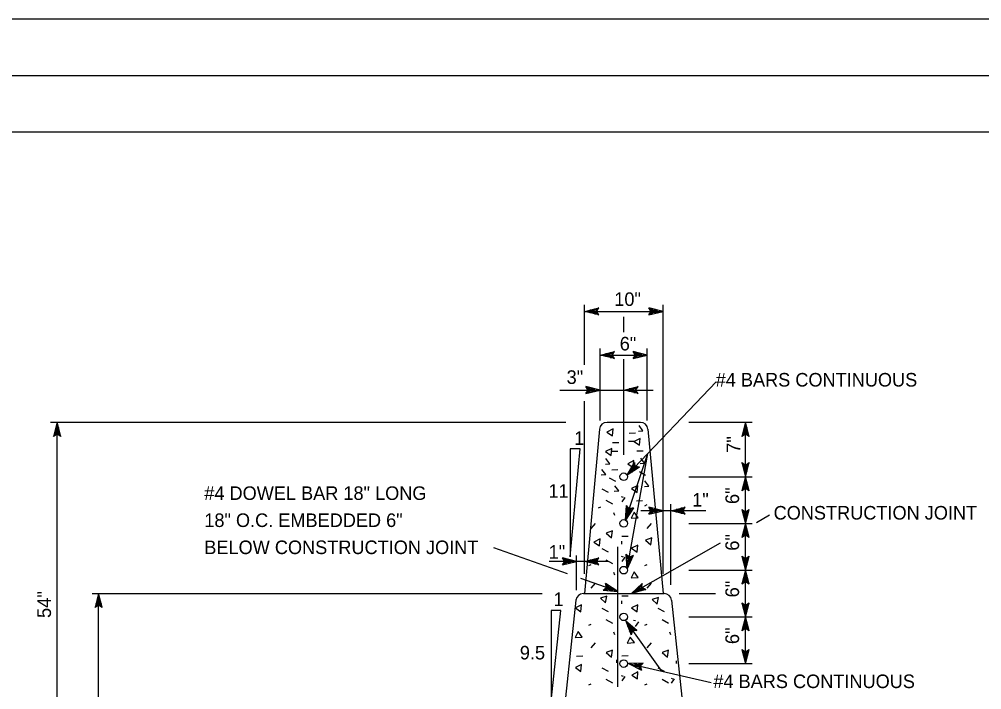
# Model space of a CAD drawing. Extents: x 504255 to 505955, y 659986 to 661086.
# Drawn here: x 504611.9 to 505019.2, y 660802.7 to 661086.4 of the extents above; entities that cross this region are included whole.
import ezdxf

# ---------------------------------------------------------------- set-up
doc = ezdxf.new("R2010")
doc.units = 0
for name, color, linetype in [('Level 62', 7, 'Continuous'), ('Level1', 7, 'Continuous'), ('Level3', 7, 'Continuous'), ('Level63', 7, 'Continuous')]:
    doc.layers.add(name, color=color, linetype=linetype)

msp = doc.modelspace()

# ---------------------------------------------------------------- linework, layer by layer
at = {"layer": 'Level 62'}
msp.add_lwpolyline([(505955.48, 661086.39), (504255.48, 661086.39), (504255.48, 659986.39), (505955.48, 659986.39)], close=True, dxfattribs=at)
at = {"layer": 'Level1'}
for p, q in [((504851.06, 660940.25), (504851.06, 660965.56)), ((504884.31, 660851.82), (504884.31, 660965.56)), ((504851.06, 660962.8), (504884.31, 660962.8)), ((504867.69, 660954), (504867.69, 660960.5)), ((504857.71, 660916.58), (504857.71, 660947.1)), ((504877.66, 660916.58), (504877.66, 660947.1)), ((504857.71, 660944.33), (504877.66, 660944.33)), ((504867.69, 660902.12), (504867.69, 660942.56)), ((504869.16, 660893.53), (504906.75, 660933.02)), ((504840.66, 660929.49), (504880.16, 660929.49)), ((504851.06, 660851.82), (504851.06, 660924.85)), ((504625.17, 660915.87), (504843.24, 660915.87)), ((504627.96, 660738.11), (504627.96, 660915.87)), ((504895.17, 660915.87), (504922.02, 660915.87)), ((504919.22, 660892.83), (504919.22, 660915.87)), ((504857.45, 660913), (504851.06, 660843.45)), ((504877.92, 660913), (504884.31, 660843.45)), ((504845.06, 660858.99), (504849.26, 660904.65)), ((504845.06, 660904.65), (504845.06, 660858.99)), ((504849.26, 660904.65), (504845.06, 660904.65)), ((504868.44, 660874.51), (504877.87, 660902.68)), ((504869.2, 660853.92), (504877.87, 660902.68)), ((504895.17, 660892.83), (504922.02, 660892.83)), ((504919.22, 660873.08), (504919.22, 660892.83)), ((504884.31, 660878.49), (504874.94, 660878.49)), ((504902.45, 660878.49), (504884.31, 660878.49)), ((504887.62, 660847.14), (504887.62, 660881.26)), ((504923.88, 660873.56), (504929.33, 660876.67)), ((504895.17, 660873.08), (504922.02, 660873.08)), ((504919.22, 660853.33), (504919.22, 660873.08)), ((504843.9, 660851.74), (504812.69, 660862.72)), ((504865.17, 660803.96), (504865.17, 660863.21)), ((504871.03, 660843.45), (504908.65, 660864.88)), ((504847.75, 660844.93), (504847.75, 660859.58)), ((504847.75, 660857.04), (504836.13, 660857.04)), ((504861.02, 660857.04), (504847.75, 660857.04)), ((504865.17, 660844.26), (504849.54, 660849.76)), ((504895.17, 660853.33), (504922.02, 660853.33)), ((504919.22, 660833.58), (504919.22, 660853.33)), ((504642.72, 660843.45), (504833.18, 660843.45)), ((504645.51, 660738.11), (504645.51, 660843.45)), ((504891.09, 660843.45), (504906.46, 660843.45)), ((504836.94, 660797.95), (504841, 660836.25)), ((504841, 660836.25), (504836.94, 660836.25)), ((504836.94, 660836.25), (504836.94, 660797.95)), ((504895.17, 660833.58), (504922.02, 660833.58)), ((504919.22, 660813.83), (504919.22, 660833.58)), ((504868.53, 660831.75), (504883.68, 660810.65)), ((504869.72, 660813.87), (504904.71, 660805.81)), ((504895.17, 660813.83), (504922.02, 660813.83))]:
    msp.add_line(p, q, dxfattribs=at)
for points in [[(504257.9, 660010.3), (505953.07, 660010.3), (505953.07, 661062.47), (504257.9, 661062.47), (504257.9, 660010.3)], [(504327.92, 660023.67), (505946.29, 660023.67), (505946.29, 661038.56), (504327.92, 661038.56), (504327.92, 660023.67)], [(504857.1, 660961.3), (504851.06, 660962.8), (504857.1, 660964.29), (504856.39, 660963.79), (504855.35, 660963.79), (504856.36, 660963.3), (504853.34, 660963.3), (504856.02, 660962.8), (504853.34, 660962.3), (504856.36, 660962.3), (504855.35, 660961.8), (504856.39, 660961.8), (504857.1, 660961.3), (504856.09, 660962.8), (504857.1, 660964.29)], [(504878.27, 660961.3), (504884.31, 660962.8), (504878.27, 660964.29), (504878.98, 660963.79), (504880.02, 660963.79), (504879.01, 660963.3), (504882.03, 660963.3), (504879.35, 660962.8), (504882.03, 660962.3), (504879.01, 660962.3), (504880.02, 660961.8), (504878.98, 660961.8), (504878.27, 660961.3), (504879.28, 660962.8), (504878.27, 660964.29)], [(504863.75, 660942.84), (504857.71, 660944.33), (504863.75, 660945.84), (504863.04, 660945.34), (504862.01, 660945.34), (504863.01, 660944.84), (504859.99, 660944.84), (504862.67, 660944.33), (504859.99, 660943.84), (504863.01, 660943.84), (504862.01, 660943.34), (504863.04, 660943.34), (504863.75, 660942.84), (504862.74, 660944.33), (504863.75, 660945.84)], [(504871.62, 660942.84), (504877.66, 660944.33), (504871.62, 660945.84), (504872.33, 660945.34), (504873.37, 660945.34), (504872.36, 660944.84), (504875.38, 660944.84), (504872.7, 660944.33), (504875.38, 660943.84), (504872.36, 660943.84), (504873.37, 660943.34), (504872.33, 660943.34), (504871.62, 660942.84), (504872.62, 660944.33), (504871.62, 660945.84)], [(504851.67, 660928), (504857.71, 660929.49), (504851.67, 660931), (504852.38, 660930.5), (504853.42, 660930.5), (504852.41, 660930), (504855.43, 660930), (504852.75, 660929.49), (504855.43, 660929), (504852.41, 660929), (504853.42, 660928.5), (504852.38, 660928.5), (504851.67, 660928), (504852.68, 660929.49), (504851.67, 660931)], [(504873.73, 660928), (504867.69, 660929.49), (504873.73, 660931), (504873.02, 660930.5), (504871.98, 660930.5), (504872.98, 660930), (504869.96, 660930), (504872.64, 660929.49), (504869.96, 660929), (504872.98, 660929), (504871.98, 660928.5), (504873.02, 660928.5), (504873.73, 660928), (504872.72, 660929.49), (504873.73, 660931)], [(504629.47, 660909.89), (504627.96, 660915.87), (504626.45, 660909.89), (504626.96, 660910.6), (504626.96, 660911.63), (504627.46, 660910.63), (504627.46, 660913.62), (504627.96, 660910.96), (504628.47, 660913.62), (504628.47, 660910.63), (504628.97, 660911.63), (504628.97, 660910.6), (504629.47, 660909.89), (504627.96, 660910.89), (504626.45, 660909.89)], [(504860.62, 660915.87), (504874.74, 660915.87)], [(504920.74, 660909.89), (504919.22, 660915.87), (504917.72, 660909.89), (504918.22, 660910.6), (504918.22, 660911.63), (504918.72, 660910.63), (504918.72, 660913.63), (504919.22, 660910.96), (504919.73, 660913.63), (504919.73, 660910.63), (504920.23, 660911.63), (504920.23, 660910.6), (504920.74, 660909.89), (504919.22, 660910.89), (504917.72, 660909.89)], [(504874.39, 660896.85), (504869.16, 660893.53), (504872.2, 660898.9), (504872.07, 660898.04), (504871.36, 660897.29), (504872.42, 660897.68), (504870.35, 660895.5), (504872.55, 660897.1), (504871.07, 660894.82), (504873.15, 660897), (504872.82, 660895.92), (504873.53, 660896.68), (504874.39, 660896.85), (504872.6, 660897.15), (504872.2, 660898.9)], [(504917.71, 660898.81), (504919.22, 660892.83), (504920.74, 660898.81), (504920.23, 660898.1), (504920.23, 660897.07), (504919.73, 660898.07), (504919.73, 660895.08), (504919.22, 660897.74), (504918.72, 660895.08), (504918.72, 660898.07), (504918.21, 660897.07), (504918.21, 660898.1), (504917.71, 660898.81), (504919.22, 660897.81), (504920.74, 660898.81)], [(504920.74, 660886.85), (504919.22, 660892.83), (504917.72, 660886.85), (504918.22, 660887.56), (504918.22, 660888.59), (504918.72, 660887.59), (504918.72, 660890.59), (504919.22, 660887.92), (504919.73, 660890.59), (504919.73, 660887.59), (504920.23, 660888.59), (504920.23, 660887.56), (504920.74, 660886.85), (504919.22, 660887.85), (504917.72, 660886.85)], [(504871.77, 660879.71), (504868.44, 660874.51), (504868.9, 660880.65), (504869.16, 660879.82), (504868.83, 660878.84), (504869.62, 660879.64), (504868.68, 660876.79), (504870, 660879.16), (504869.63, 660876.48), (504870.58, 660879.32), (504870.74, 660878.22), (504871.06, 660879.2), (504871.77, 660879.71), (504870.02, 660879.23), (504868.9, 660880.65)], [(504878.27, 660877), (504884.31, 660878.49), (504878.27, 660879.99), (504878.98, 660879.5), (504880.02, 660879.5), (504879.01, 660879), (504882.03, 660879), (504879.35, 660878.49), (504882.03, 660877.99), (504879.01, 660877.99), (504880.02, 660877.5), (504878.98, 660877.5), (504878.27, 660877), (504879.28, 660878.49), (504878.27, 660879.99)], [(504893.66, 660877), (504887.62, 660878.49), (504893.66, 660879.99), (504892.95, 660879.5), (504891.91, 660879.5), (504892.92, 660879), (504889.9, 660879), (504892.58, 660878.49), (504889.9, 660877.99), (504892.92, 660877.99), (504891.91, 660877.5), (504892.95, 660877.5), (504893.66, 660877), (504892.66, 660878.49), (504893.66, 660879.99)], [(504917.71, 660879.06), (504919.22, 660873.08), (504920.74, 660879.06), (504920.23, 660878.35), (504920.23, 660877.32), (504919.73, 660878.32), (504919.73, 660875.33), (504919.22, 660877.99), (504918.72, 660875.33), (504918.72, 660878.32), (504918.21, 660877.32), (504918.21, 660878.35), (504917.71, 660879.06), (504919.22, 660878.06), (504920.74, 660879.06)], [(504920.74, 660867.1), (504919.22, 660873.08), (504917.72, 660867.1), (504918.22, 660867.81), (504918.22, 660868.84), (504918.72, 660867.84), (504918.72, 660870.84), (504919.22, 660868.18), (504919.73, 660870.84), (504919.73, 660867.84), (504920.23, 660868.84), (504920.23, 660867.81), (504920.74, 660867.1), (504919.22, 660868.1), (504917.72, 660867.1)], [(504841.71, 660855.55), (504847.75, 660857.04), (504841.71, 660858.54), (504842.42, 660858.05), (504843.45, 660858.05), (504842.45, 660857.55), (504845.47, 660857.55), (504842.79, 660857.04), (504845.47, 660856.54), (504842.45, 660856.54), (504843.45, 660856.05), (504842.42, 660856.05), (504841.71, 660855.55), (504842.71, 660857.04), (504841.71, 660858.54)], [(504857.1, 660855.55), (504851.06, 660857.04), (504857.1, 660858.54), (504856.39, 660858.05), (504855.35, 660858.05), (504856.36, 660857.55), (504853.34, 660857.55), (504856.02, 660857.04), (504853.34, 660856.54), (504856.36, 660856.54), (504855.35, 660856.05), (504856.39, 660856.05), (504857.1, 660855.55), (504856.09, 660857.04), (504857.1, 660858.54)], [(504871.73, 660859.55), (504869.2, 660853.92), (504868.76, 660860.07), (504869.13, 660859.29), (504868.95, 660858.27), (504869.62, 660859.17), (504869.1, 660856.22), (504870.05, 660858.75), (504870.09, 660856.04), (504870.61, 660858.99), (504870.93, 660857.93), (504871.11, 660858.94), (504871.73, 660859.55), (504870.07, 660858.83), (504868.76, 660860.07)], [(504917.71, 660859.31), (504919.22, 660853.33), (504920.74, 660859.31), (504920.23, 660858.6), (504920.23, 660857.57), (504919.73, 660858.57), (504919.73, 660855.58), (504919.22, 660858.24), (504918.72, 660855.58), (504918.72, 660858.57), (504918.21, 660857.57), (504918.21, 660858.6), (504917.71, 660859.31), (504919.22, 660858.31), (504920.74, 660859.31)], [(504920.74, 660847.35), (504919.22, 660853.33), (504917.72, 660847.35), (504918.22, 660848.06), (504918.22, 660849.09), (504918.72, 660848.09), (504918.72, 660851.09), (504919.22, 660848.42), (504919.73, 660851.09), (504919.73, 660848.09), (504920.23, 660849.09), (504920.23, 660848.06), (504920.74, 660847.35), (504919.22, 660848.35), (504917.72, 660847.35)], [(504858.98, 660844.85), (504865.17, 660844.26), (504859.99, 660847.66), (504860.49, 660846.96), (504861.47, 660846.61), (504860.35, 660846.48), (504863.2, 660845.47), (504860.5, 660845.9), (504862.87, 660844.54), (504860.02, 660845.54), (504860.8, 660844.74), (504859.82, 660845.09), (504858.98, 660844.85), (504860.43, 660845.93), (504859.99, 660847.66)], [(504877.02, 660845.14), (504871.03, 660843.45), (504875.51, 660847.73), (504875.14, 660846.95), (504874.24, 660846.42), (504875.37, 660846.49), (504872.75, 660845), (504875.33, 660845.9), (504873.25, 660844.14), (504875.87, 660845.63), (504875.25, 660844.7), (504876.15, 660845.22), (504877.02, 660845.14), (504875.39, 660845.94), (504875.51, 660847.73)], [(504647.03, 660837.48), (504645.51, 660843.45), (504644, 660837.48), (504644.51, 660838.19), (504644.51, 660839.21), (504645.01, 660838.22), (504645.01, 660841.21), (504645.51, 660838.55), (504646.02, 660841.21), (504646.02, 660838.22), (504646.52, 660839.21), (504646.52, 660838.19), (504647.03, 660837.48), (504645.51, 660838.48), (504644, 660837.48)], [(504850.6, 660843.45), (504884.76, 660843.45)], [(504847.43, 660840.63), (504841.09, 660780.9)], [(504887.94, 660840.63), (504897.78, 660747.99)], [(504917.71, 660839.56), (504919.22, 660833.58), (504920.74, 660839.56), (504920.23, 660838.85), (504920.23, 660837.83), (504919.73, 660838.82), (504919.73, 660835.83), (504919.22, 660838.49), (504918.72, 660835.83), (504918.72, 660838.82), (504918.21, 660837.83), (504918.21, 660838.85), (504917.71, 660839.56), (504919.22, 660838.56), (504920.74, 660839.56)], [(504920.74, 660827.61), (504919.22, 660833.58), (504917.72, 660827.61), (504918.22, 660828.31), (504918.22, 660829.34), (504918.72, 660828.35), (504918.72, 660831.34), (504919.22, 660828.68), (504919.73, 660831.34), (504919.73, 660828.35), (504920.23, 660829.34), (504920.23, 660828.31), (504920.74, 660827.61), (504919.22, 660828.6), (504917.72, 660827.61)], [(504873.26, 660827.75), (504868.53, 660831.75), (504870.8, 660826.01), (504870.79, 660826.88), (504870.19, 660827.72), (504871.19, 660827.19), (504869.44, 660829.64), (504871.4, 660827.75), (504870.25, 660830.21), (504872.01, 660827.77), (504871.83, 660828.88), (504872.43, 660828.03), (504873.26, 660827.75), (504871.45, 660827.69), (504870.8, 660826.01)], [(504917.71, 660819.81), (504919.22, 660813.83), (504920.74, 660819.81), (504920.23, 660819.1), (504920.23, 660818.07), (504919.73, 660819.07), (504919.73, 660816.08), (504919.22, 660818.74), (504918.72, 660816.08), (504918.72, 660819.07), (504918.21, 660818.07), (504918.21, 660819.1), (504917.71, 660819.81), (504919.22, 660818.81), (504920.74, 660819.81)], [(504875.94, 660813.97), (504869.72, 660813.87), (504875.26, 660811.06), (504874.68, 660811.71), (504873.66, 660811.94), (504874.76, 660812.2), (504871.81, 660812.88), (504874.55, 660812.76), (504872.04, 660813.85), (504874.99, 660813.17), (504874.12, 660813.88), (504875.13, 660813.64), (504875.94, 660813.97), (504874.62, 660812.74), (504875.26, 660811.06)]]:
    msp.add_lwpolyline(points, dxfattribs=at)
for centre, start_param, end_param in [((504860.63, 660912.71), 4.712389, 6.192092), ((504874.75, 660912.71), 3.232686, 4.712389), ((504850.61, 660840.3), 4.712389, 6.178514), ((504884.77, 660840.3), 3.24706, 4.712389)]:
    msp.add_ellipse(centre, major_axis=(-3.19, 0), ratio=0.99, start_param=start_param, end_param=end_param, dxfattribs=at)
at = {"layer": 'Level3'}
for p, q in [((504872.64, 660911.23), (504870.03, 660911.19)), ((504865.59, 660907.21), (504862.98, 660907.16)), ((504872.29, 660907.8), (504869.67, 660907.75)), ((504865.24, 660903.54), (504862.62, 660903.49)), ((504875.87, 660903.66), (504873.26, 660903.61)), ((504865.24, 660895.72), (504862.62, 660895.68)), ((504874.31, 660895.08), (504876.92, 660893.54)), ((504861.54, 660892.45), (504864.19, 660891.04)), ((504858.43, 660887.71), (504861.08, 660886.3)), ((504860.18, 660882.99), (504862.92, 660881.38)), ((504867.58, 660884.14), (504866.8, 660884.37)), ((504868.17, 660884.14), (504866.85, 660882.28)), ((504875.63, 660882.59), (504873.02, 660882.54)), ((504857, 660879.66), (504857.94, 660880.1)), ((504876.64, 660880.61), (504877.58, 660881.05)), ((504863.29, 660877.73), (504863.84, 660876.59)), ((504855.55, 660873.09), (504853.71, 660870.97)), ((504879.25, 660873.09), (504877.42, 660870.97)), ((504869.54, 660867.56), (504866.93, 660867.51)), ((504858.43, 660862.46), (504861.08, 660861.05)), ((504866.8, 660865.58), (504866.8, 660864.39)), ((504860.18, 660857.73), (504862.92, 660856.12)), ((504867.58, 660858.89), (504866.8, 660859.12)), ((504868.17, 660858.89), (504866.85, 660857.03)), ((504852.94, 660855.36), (504853.88, 660855.79)), ((504876.64, 660855.36), (504877.58, 660855.79)), ((504863.29, 660852.48), (504863.84, 660851.34)), ((504855.55, 660847.84), (504853.71, 660845.71)), ((504879.25, 660847.84), (504877.42, 660845.71)), ((504869.54, 660842.31), (504866.93, 660842.26)), ((504858.43, 660837.2), (504861.08, 660835.79)), ((504866.8, 660840.32), (504866.8, 660839.14)), ((504882.13, 660837.2), (504884.78, 660835.79)), ((504852.94, 660830.11), (504853.88, 660830.54)), ((504860.18, 660832.47), (504862.92, 660830.87)), ((504872.61, 660831.84), (504871.83, 660832.07)), ((504873.88, 660831.41), (504872.56, 660829.56)), ((504876.64, 660830.11), (504877.58, 660830.54)), ((504883.88, 660832.47), (504886.62, 660830.87)), ((504863.29, 660827.22), (504863.84, 660826.08)), ((504886.98, 660827.22), (504887.54, 660826.08)), ((504855.55, 660822.58), (504853.71, 660820.46)), ((504879.25, 660822.58), (504877.42, 660820.46)), ((504850.34, 660816.9), (504847.72, 660816.84)), ((504869.54, 660817.05), (504866.93, 660817)), ((504864.62, 660815.38), (504864.62, 660814.19)), ((504889.9, 660815.01), (504889.9, 660813.83)), ((504858.43, 660811.95), (504861.08, 660810.54)), ((504882.13, 660811.95), (504884.78, 660810.54)), ((504852.94, 660804.86), (504853.88, 660805.28)), ((504860.18, 660807.22), (504862.92, 660805.61)), ((504867.58, 660808.38), (504866.8, 660808.61)), ((504868.17, 660808.38), (504866.85, 660806.53)), ((504876.64, 660804.86), (504877.58, 660805.28)), ((504883.88, 660807.22), (504886.62, 660805.61)), ((504889, 660807.32), (504887.69, 660805.46)), ((504888.66, 660807.2), (504887.87, 660807.43))]:
    msp.add_line(p, q, dxfattribs=at)
for points in [[(504860.57, 660911.76), (504862.9, 660910.16), (504863.18, 660913.1)], [(504872.04, 660907.73), (504874.37, 660906.14), (504874.65, 660909.08)], [(504859.97, 660903.47), (504862.31, 660901.87), (504862.59, 660904.82)], [(504869.41, 660898.38), (504871.74, 660896.79), (504872.02, 660899.73)], [(504870.97, 660887.85), (504873.3, 660886.25), (504873.58, 660889.19)], [(504872.04, 660877.84), (504870.85, 660875.3), (504873.83, 660875.52)], [(504862.97, 660869.92), (504860.29, 660869.03), (504862.5, 660867.04)], [(504855.04, 660865.2), (504857.36, 660863.61), (504857.65, 660866.55)], [(504879.61, 660866.96), (504876.93, 660866.07), (504879.14, 660864.08)], [(504870.97, 660862.59), (504873.3, 660861.01), (504873.58, 660863.94)], [(504872.04, 660852.59), (504870.85, 660850.05), (504873.83, 660850.27)], [(504860.49, 660842.35), (504857.81, 660841.46), (504860.02, 660839.48)], [(504882.36, 660841.83), (504879.68, 660840.93), (504881.89, 660838.95)], [(504847.27, 660837.34), (504849.59, 660835.75), (504849.88, 660838.69)], [(504870.97, 660837.34), (504873.3, 660835.75), (504873.58, 660838.69)], [(504848.35, 660827.34), (504847.16, 660824.79), (504850.13, 660825.02)], [(504870.39, 660825.01), (504869.2, 660822.47), (504872.18, 660822.7)], [(504862.97, 660819.42), (504860.29, 660818.52), (504862.5, 660816.54)], [(504886.67, 660819.42), (504883.99, 660818.52), (504886.2, 660816.54)], [(504847.27, 660812.09), (504849.59, 660810.5), (504849.88, 660813.43)], [(504871.11, 660808.94), (504873.44, 660807.36), (504873.72, 660810.29)]]:
    msp.add_lwpolyline(points, close=True, dxfattribs=at)
for points in [[(504873.92, 660912.19), (504875.82, 660912.33), (504874.16, 660914.5)], [(504859.94, 660898.23), (504861.84, 660898.36), (504860.18, 660900.53)], [(504874.63, 660898.46), (504876.53, 660898.6), (504874.88, 660900.76)], [(504858.15, 660893.61), (504860.04, 660893.75), (504858.39, 660895.92)], [(504876.43, 660888.76), (504878.32, 660888.89), (504876.67, 660891.06)], [(504863.64, 660886.75), (504865.54, 660886.89), (504863.88, 660889.05)]]:
    msp.add_lwpolyline(points, dxfattribs=at)
at = {"layer": 'Level63'}
for centre in [(504867.69, 660892.83), (504867.69, 660873.08), (504867.69, 660853.33), (504867.69, 660833.58), (504867.69, 660813.83)]:
    msp.add_ellipse(centre, major_axis=(1.63, 0), ratio=0.99, dxfattribs=at)

# ---------------------------------------------------------------- texts
at = {"layer": 'Level1'}
for s, height, p in [('10"', 5.739, (504863.69, 660965.11)), ('6"', 5.739, (504865.99, 660946.29)), ('3"', 5.739, (504843.52, 660932.12)), ('#4 BARS CONTINUOUS', 5.7392, (504906.58, 660931.01)), ('1', 5.74, (504846.72, 660906.32)), ('#4 DOWEL BAR 18" LONG', 5.7392, (504690.21, 660883.04)), ('11', 5.739, (504835.83, 660883.97)), ('1"', 5.739, (504896.66, 660880.21)), ('CONSTRUCTION JOINT', 5.7392, (504931.1, 660874.74)), ('18" O.C. EMBEDDED 6"', 5.7392, (504690.21, 660871.59)), ('BELOW CONSTRUCTION JOINT', 5.7392, (504690.21, 660860.13)), ('1"', 5.739, (504835.92, 660858.17)), ('1', 5.74, (504837.98, 660838.17)), ('9.5', 5.739, (504823.72, 660815.56)), ('#4 BARS CONTINUOUS', 5.7392, (504905.61, 660803.44))]:
    msp.add_text(s, height=height, dxfattribs=at).set_placement(p)
for s, p in [('7"', (504916.98, 660902.94)), ('6"', (504916.49, 660881.29)), ('6"', (504916.49, 660861.54)), ('6"', (504916.49, 660841.8)), ('54"', (504625.34, 660833.09)), ('6"', (504916.49, 660822.04))]:
    msp.add_text(s, height=5.797, rotation=90, dxfattribs=at).set_placement(p)

doc.saveas('drawing.dxf')
